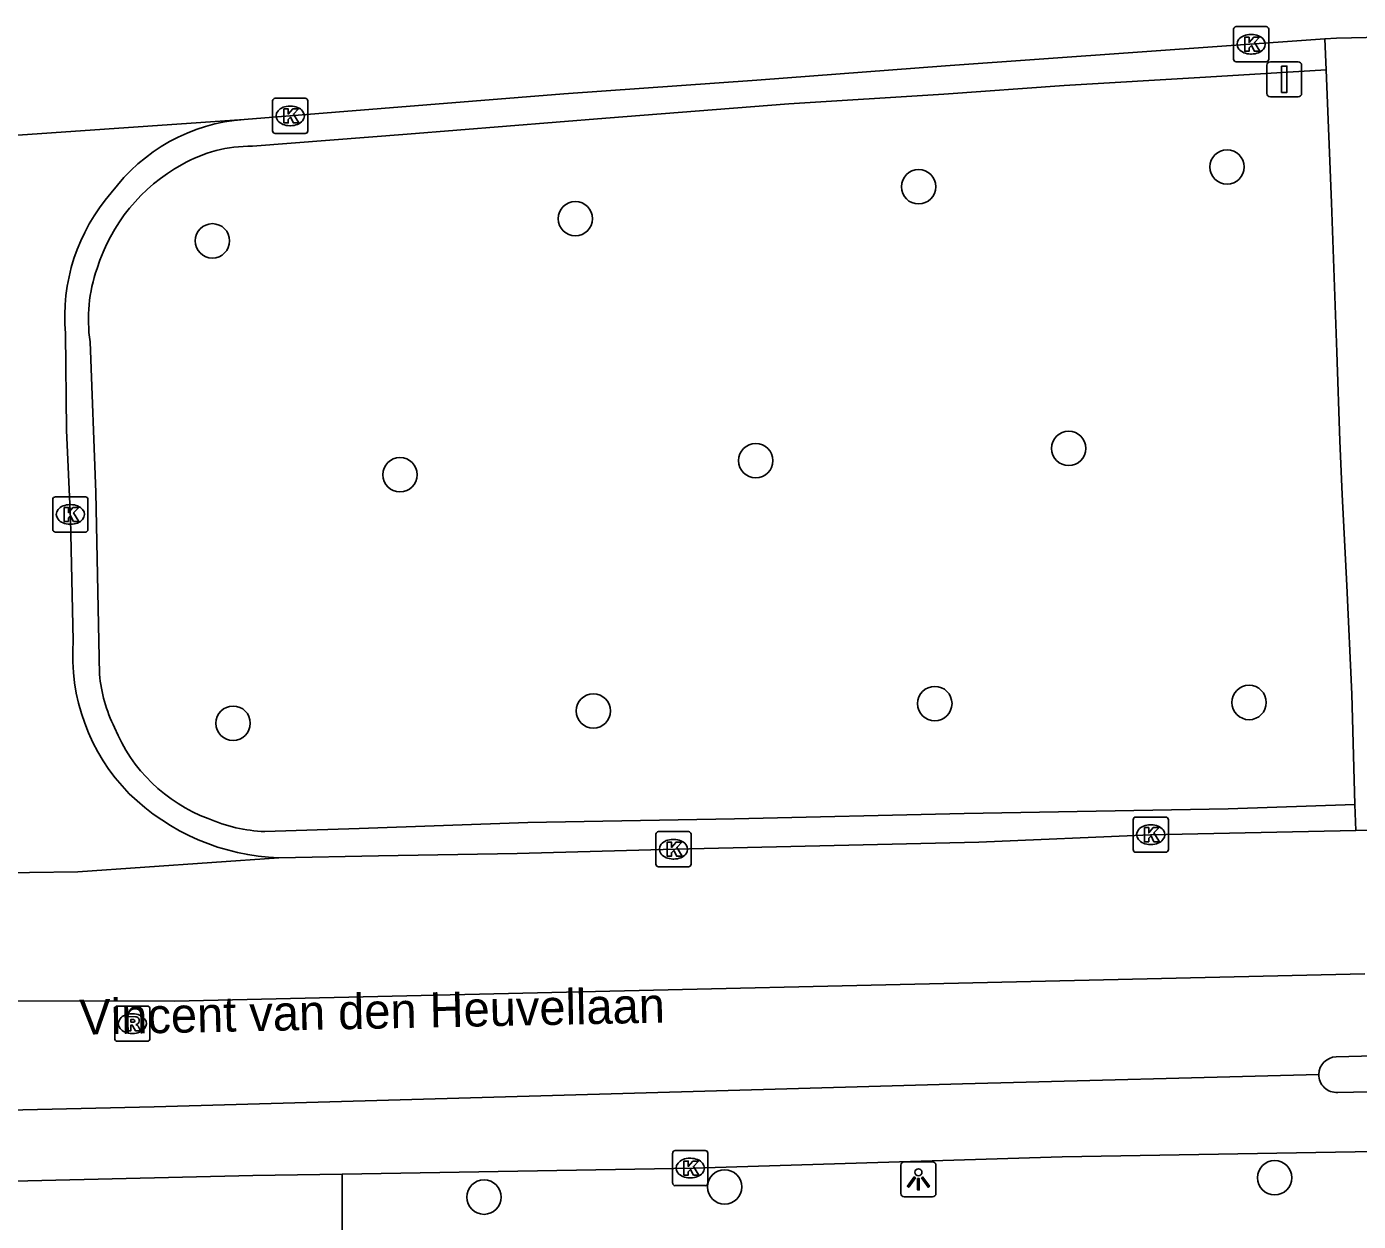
# Model space of a CAD drawing. Extents: x 160806 to 161707, y 383697 to 384148.
# Drawn here: x 161330.97 to 161368.85, y 384111.62 to 384145.6 of the extents above; entities that cross this region are included whole.
import ezdxf

# ---------------------------------------------------------------- set-up
doc = ezdxf.new("R2010")
doc.units = 0
for name, color, linetype in [('IMGEO_Boom', 7, 'Continuous'), ('IMGEO_Kolk', 7, 'Continuous'), ('IMGEO_Lichtpunt', 7, 'Continuous'), ('IMGEO_Openbare_ruimte_label', 7, 'Continuous'), ('IMGEO_Rijbaan_lokaal_gesloten', 7, 'Continuous'), ('IMGEO_Rioolput', 7, 'Continuous'), ('IMGEO_Verkeersbordpaal', 7, 'Continuous'), ('IMGEO_Verkeerseiland_open', 7, 'Continuous'), ('IMGEO_Voetpad_open', 7, 'Continuous')]:
    doc.layers.add(name, color=color, linetype=linetype)

msp = doc.modelspace()

# ---------------------------------------------------------------- linework, layer by layer
at = {"layer": 'IMGEO_Boom'}
for centre in [(161365.116, 384141.61), (161356.343, 384141.046), (161346.581, 384140.138), (161336.259, 384139.508), (161360.612, 384133.603), (161351.712, 384133.255), (161341.593, 384132.854), (161356.804, 384126.346), (161365.743, 384126.376), (161347.092, 384126.136), (161336.846, 384125.786), (161350.826, 384112.597), (161366.469, 384112.857), (161343.983, 384112.305)]:
    msp.add_circle(centre, 0.489, dxfattribs=at)
at = {"layer": 'IMGEO_Kolk'}
for p, q in [((161365.375, 384145.601), (161366.227, 384145.601)), ((161365.3, 384144.675), (161365.3, 384145.527)), ((161365.788, 384145.381), (161365.813, 384145.381)), ((161366.301, 384145.527), (161366.301, 384144.675)), ((161366.227, 384144.601), (161365.375, 384144.601)), ((161365.811, 384144.821), (161365.786, 384144.821)), ((161337.971, 384142.637), (161337.971, 384143.489)), ((161338.046, 384143.563), (161338.898, 384143.563)), ((161338.459, 384143.343), (161338.484, 384143.343)), ((161338.972, 384143.489), (161338.972, 384142.637)), ((161338.482, 384142.783), (161338.457, 384142.783)), ((161338.898, 384142.563), (161338.046, 384142.563)), ((161331.717, 384131.299), (161331.717, 384132.151)), ((161331.792, 384132.225), (161332.644, 384132.225)), ((161332.205, 384132.005), (161332.23, 384132.005)), ((161332.718, 384132.151), (161332.718, 384131.299)), ((161332.644, 384131.225), (161331.792, 384131.225)), ((161332.228, 384131.445), (161332.203, 384131.445)), ((161362.445, 384122.19), (161362.445, 384123.042)), ((161362.52, 384123.116), (161363.372, 384123.116)), ((161362.933, 384122.896), (161362.958, 384122.896)), ((161363.446, 384123.042), (161363.446, 384122.19)), ((161348.871, 384121.777), (161348.871, 384122.629)), ((161348.946, 384122.703), (161349.798, 384122.703)), ((161349.872, 384122.629), (161349.872, 384121.777)), ((161349.359, 384122.483), (161349.384, 384122.483)), ((161363.372, 384122.116), (161362.52, 384122.116)), ((161362.956, 384122.336), (161362.931, 384122.336)), ((161349.382, 384121.923), (161349.357, 384121.923)), ((161349.798, 384121.703), (161348.946, 384121.703)), ((161349.348, 384112.706), (161349.348, 384113.558)), ((161349.423, 384113.632), (161350.275, 384113.632)), ((161349.836, 384113.412), (161349.861, 384113.412)), ((161350.349, 384113.558), (161350.349, 384112.706)), ((161349.859, 384112.852), (161349.834, 384112.852)), ((161350.275, 384112.632), (161349.423, 384112.632))]:
    msp.add_line(p, q, dxfattribs=at)
for points in [[(161365.375, 384145.601), (161366.227, 384145.601)], [(161365.3, 384144.675), (161365.3, 384145.527)], [(161365.621, 384145.301), (161365.744, 384145.301), (161365.744, 384145.15), (161365.874, 384145.301), (161366.038, 384145.301), (161365.892, 384145.15), (161366.045, 384144.901), (161365.893, 384144.901), (161365.808, 384145.065), (161365.744, 384144.998), (161365.744, 384144.901), (161365.621, 384144.901), (161365.621, 384145.301)], [(161366.301, 384145.527), (161366.301, 384144.675)], [(161366.227, 384144.601), (161365.375, 384144.601)], [(161337.971, 384142.637), (161337.971, 384143.489)], [(161338.046, 384143.563), (161338.898, 384143.563)], [(161338.972, 384143.489), (161338.972, 384142.637)], [(161338.292, 384143.263), (161338.415, 384143.263), (161338.415, 384143.112), (161338.545, 384143.263), (161338.709, 384143.263), (161338.563, 384143.112), (161338.716, 384142.863), (161338.564, 384142.863), (161338.479, 384143.027), (161338.415, 384142.96), (161338.415, 384142.863), (161338.292, 384142.863), (161338.292, 384143.263)], [(161338.898, 384142.563), (161338.046, 384142.563)], [(161331.717, 384131.299), (161331.717, 384132.151)], [(161331.792, 384132.225), (161332.644, 384132.225)], [(161332.718, 384132.151), (161332.718, 384131.299)], [(161332.038, 384131.925), (161332.161, 384131.925), (161332.161, 384131.774), (161332.291, 384131.925), (161332.455, 384131.925), (161332.309, 384131.774), (161332.462, 384131.525), (161332.31, 384131.525), (161332.225, 384131.689), (161332.161, 384131.622), (161332.161, 384131.525), (161332.038, 384131.525), (161332.038, 384131.925)], [(161332.644, 384131.225), (161331.792, 384131.225)], [(161362.445, 384122.19), (161362.445, 384123.042)], [(161362.52, 384123.116), (161363.372, 384123.116)], [(161363.446, 384123.042), (161363.446, 384122.19)], [(161348.871, 384121.777), (161348.871, 384122.629)], [(161348.946, 384122.703), (161349.798, 384122.703)], [(161349.872, 384122.629), (161349.872, 384121.777)], [(161362.766, 384122.816), (161362.889, 384122.816), (161362.889, 384122.665), (161363.019, 384122.816), (161363.183, 384122.816), (161363.037, 384122.665), (161363.19, 384122.416), (161363.038, 384122.416), (161362.953, 384122.58), (161362.889, 384122.513), (161362.889, 384122.416), (161362.766, 384122.416), (161362.766, 384122.816)], [(161349.192, 384122.403), (161349.315, 384122.403), (161349.315, 384122.252), (161349.445, 384122.403), (161349.609, 384122.403), (161349.463, 384122.252), (161349.616, 384122.003), (161349.464, 384122.003), (161349.379, 384122.167), (161349.315, 384122.1), (161349.315, 384122.003), (161349.192, 384122.003), (161349.192, 384122.403)], [(161363.372, 384122.116), (161362.52, 384122.116)], [(161349.798, 384121.703), (161348.946, 384121.703)], [(161349.348, 384112.706), (161349.348, 384113.558)], [(161349.423, 384113.632), (161350.275, 384113.632)], [(161350.349, 384113.558), (161350.349, 384112.706)], [(161349.669, 384113.332), (161349.792, 384113.332), (161349.792, 384113.181), (161349.922, 384113.332), (161350.086, 384113.332), (161349.94, 384113.181), (161350.093, 384112.932), (161349.941, 384112.932), (161349.856, 384113.096), (161349.792, 384113.029), (161349.792, 384112.932), (161349.669, 384112.932), (161349.669, 384113.332)], [(161350.275, 384112.632), (161349.423, 384112.632)]]:
    msp.add_lwpolyline(points, dxfattribs=at)
for centre, start, end in [((161365.377, 384145.525), 91.552, 178.448), ((161365.377, 384145.525), 91.552, 178.448), ((161366.225, 384145.525), 1.552, 88.448), ((161366.225, 384145.525), 1.552, 88.448), ((161365.377, 384144.677), 181.552, 268.448), ((161365.377, 384144.677), 181.552, 268.448), ((161366.225, 384144.677), 271.552, 358.448), ((161366.225, 384144.677), 271.552, 358.448), ((161338.048, 384143.487), 91.552, 178.448), ((161338.048, 384143.487), 91.552, 178.448), ((161338.896, 384143.487), 1.552, 88.448), ((161338.896, 384143.487), 1.552, 88.448), ((161338.048, 384142.639), 181.552, 268.448), ((161338.048, 384142.639), 181.552, 268.448), ((161338.896, 384142.639), 271.552, 358.448), ((161338.896, 384142.639), 271.552, 358.448), ((161331.794, 384132.149), 91.552, 178.448), ((161331.794, 384132.149), 91.552, 178.448), ((161332.642, 384132.149), 1.552, 88.448), ((161332.642, 384132.149), 1.552, 88.448), ((161331.794, 384131.301), 181.552, 268.448), ((161331.794, 384131.301), 181.552, 268.448), ((161332.642, 384131.301), 271.552, 358.448), ((161332.642, 384131.301), 271.552, 358.448), ((161362.522, 384123.04), 91.552, 178.448), ((161362.522, 384123.04), 91.552, 178.448), ((161363.37, 384123.04), 1.552, 88.448), ((161363.37, 384123.04), 1.552, 88.448), ((161348.948, 384122.627), 91.552, 178.448), ((161348.948, 384122.627), 91.552, 178.448), ((161349.796, 384122.627), 1.552, 88.448), ((161349.796, 384122.627), 1.552, 88.448), ((161362.522, 384122.192), 181.552, 268.448), ((161362.522, 384122.192), 181.552, 268.448), ((161363.37, 384122.192), 271.552, 358.448), ((161363.37, 384122.192), 271.552, 358.448), ((161348.948, 384121.779), 181.552, 268.448), ((161348.948, 384121.779), 181.552, 268.448), ((161349.796, 384121.779), 271.552, 358.448), ((161349.796, 384121.779), 271.552, 358.448), ((161349.425, 384113.556), 91.552, 178.448), ((161349.425, 384113.556), 91.552, 178.448), ((161350.273, 384113.556), 1.552, 88.448), ((161350.273, 384113.556), 1.552, 88.448), ((161349.425, 384112.708), 181.552, 268.448), ((161349.425, 384112.708), 181.552, 268.448), ((161350.273, 384112.708), 271.552, 358.448), ((161350.273, 384112.708), 271.552, 358.448)]:
    msp.add_arc(centre, 0.0765, start, end, dxfattribs=at)
for centre, major_axis, ratio, start_param, end_param in [((161365.787, 384145.101), (-0.387, 0.002), 0.722429, 4.712389, 7.853982), ((161365.812, 384145.101), (-0.39, 0.002), 0.717154, 1.570796, 4.712389), ((161338.458, 384143.063), (-0.387, 0.002), 0.722429, 4.712389, 7.853982), ((161338.483, 384143.063), (-0.39, 0.002), 0.717154, 1.570796, 4.712389), ((161332.204, 384131.725), (-0.387, 0.002), 0.722429, 4.712389, 7.853982), ((161332.229, 384131.725), (-0.39, 0.002), 0.717154, 1.570796, 4.712389), ((161362.932, 384122.616), (-0.387, 0.002), 0.722429, 4.712389, 7.853982), ((161362.957, 384122.616), (-0.39, 0.002), 0.717154, 1.570796, 4.712389), ((161349.358, 384122.203), (-0.387, 0.002), 0.722429, 4.712389, 7.853982), ((161349.383, 384122.203), (-0.39, 0.002), 0.717154, 1.570796, 4.712389), ((161349.835, 384113.132), (-0.387, 0.002), 0.722429, 4.712389, 7.853982), ((161349.86, 384113.132), (-0.39, 0.002), 0.717154, 1.570796, 4.712389)]:
    msp.add_ellipse(centre, major_axis=major_axis, ratio=ratio, start_param=start_param, end_param=end_param, dxfattribs=at)
at = {"layer": 'IMGEO_Lichtpunt'}
for p, q in [((161355.84, 384113.215), (161355.84, 384112.408)), ((161355.84, 384113.215), (161355.84, 384112.408)), ((161356.742, 384113.31), (161355.934, 384113.31)), ((161356.742, 384113.31), (161355.934, 384113.31)), ((161356.836, 384112.408), (161356.836, 384113.215)), ((161356.836, 384112.408), (161356.836, 384113.215)), ((161355.934, 384112.314), (161356.742, 384112.314)), ((161355.934, 384112.314), (161356.742, 384112.314))]:
    msp.add_line(p, q, dxfattribs=at)
for points in [[(161356.214, 384112.879), (161356.253, 384112.851), (161356.065, 384112.589), (161356.027, 384112.616), (161356.214, 384112.879)], [(161356.316, 384112.831), (161356.363, 384112.831), (161356.363, 384112.509), (161356.316, 384112.509), (161356.316, 384112.831)], [(161356.426, 384112.851), (161356.464, 384112.878), (161356.651, 384112.616), (161356.612, 384112.588), (161356.426, 384112.851)]]:
    msp.add_lwpolyline(points, dxfattribs=at)
msp.add_circle((161356.339, 384113.013), 0.0994, dxfattribs=at)
for centre, start, end in [((161355.934, 384113.215), 90, 180), ((161355.934, 384113.215), 90, 180), ((161356.742, 384113.215), 0, 90), ((161356.742, 384113.215), 0, 90), ((161355.934, 384112.408), 180, 270), ((161355.934, 384112.408), 180, 270), ((161356.742, 384112.408), 270, 0), ((161356.742, 384112.408), 270, 360)]:
    msp.add_arc(centre, 0.0946, start, end, dxfattribs=at)
at = {"layer": 'IMGEO_Rijbaan_lokaal_gesloten'}
for points in [[(161337.16, 384142.963), (161346.257, 384143.694), (161351.743, 384144.08), (161357.112, 384144.482), (161367.896, 384145.252)], [(161367.896, 384145.252), (161368.23, 384145.276), (161372.889, 384145.38)], [(161317.535, 384141.567), (161327.703, 384142.304), (161337.16, 384142.963)], [(161332.082, 384136.87), (161332.111, 384134.119), (161332.223, 384131.597), (161332.301, 384128.136)], [(161338.149, 384121.956), (161340.98, 384122.012), (161344.922, 384122.082), (161349.424, 384122.203), (161358.059, 384122.401), (161362.942, 384122.615), (161368.776, 384122.738)], [(161373.645, 384122.84), (161368.776, 384122.738)], [(161338.149, 384121.956), (161332.428, 384121.56), (161328.301, 384121.504), (161324.44, 384121.451), (161317.569, 384121.54)], [(161260.613, 384121.23), (161278.23, 384120.232), (161293.967, 384119.32), (161308.839, 384118.481), (161316.729, 384118.038), (161322.396, 384117.897), (161335.182, 384117.881), (161369.031, 384118.661)], [(161367.726, 384115.798), (161357.592, 384115.525), (161334.603, 384114.873), (161327.538, 384114.71), (161321.017, 384114.547), (161306.289, 384115.145), (161286.376, 384116.275)], [(161372.197, 384116.403), (161368.215, 384116.296)], [(161368.263, 384115.283), (161372.247, 384115.365)], [(161428.175, 384115.173), (161420.828, 384114.943), (161412.541, 384114.668), (161402.739, 384114.468), (161394.707, 384114.341), (161383.418, 384113.963), (161372.09, 384113.647), (161360.425, 384113.454), (161349.937, 384113.134), (161339.944, 384112.961)], [(161339.944, 384112.961), (161337.406, 384112.917), (161325.397, 384112.64), (161323.478, 384112.593)]]:
    msp.add_lwpolyline(points, dxfattribs=at)
for centre, radius, start, end in [((161337.542, 384137.818), 5.16, 94.2466, 143.7156), ((161337.391, 384137.356), 5.331, 138.745, 185.2292), ((161337.886, 384127.711), 5.601, 175.6469, 224.5599), ((161338.39, 384128.388), 6.437, 225.7072, 267.8533), ((161368.234, 384115.789), 0.508, 92.0985, 178.9464), ((161368.234, 384115.79), 0.508, 179.1481, 273.248)]:
    msp.add_arc(centre, radius, start, end, dxfattribs=at)
at = {"layer": 'IMGEO_Rioolput'}
for p, q in [((161333.48, 384116.814), (161333.48, 384117.666)), ((161333.555, 384117.74), (161334.407, 384117.74)), ((161334.481, 384117.666), (161334.481, 384116.814)), ((161333.968, 384117.52), (161333.993, 384117.52)), ((161333.991, 384116.96), (161333.966, 384116.96)), ((161334.407, 384116.74), (161333.555, 384116.74))]:
    msp.add_line(p, q, dxfattribs=at)
for points in [[(161333.48, 384116.814), (161333.48, 384117.666)], [(161333.555, 384117.74), (161334.407, 384117.74)], [(161334.481, 384117.666), (161334.481, 384116.814)], [(161334.069, 384117.438), (161333.817, 384117.44), (161333.817, 384117.04)], [(161333.817, 384117.04), (161333.941, 384117.04), (161333.941, 384117.202), (161333.952, 384117.202)], [(161333.995, 384117.359), (161333.941, 384117.359), (161333.941, 384117.278)], [(161333.941, 384117.278), (161333.993, 384117.278)], [(161333.999, 384117.173), (161334.07, 384117.04), (161334.21, 384117.04), (161334.145, 384117.166)], [(161334.407, 384116.74), (161333.555, 384116.74)]]:
    msp.add_lwpolyline(points, dxfattribs=at)
for centre, radius, start, end in [((161333.557, 384117.664), 0.0765, 91.552, 178.448), ((161333.557, 384117.664), 0.0765, 91.552, 178.448), ((161334.405, 384117.664), 0.0765, 1.552, 88.448), ((161334.405, 384117.664), 0.0765, 1.552, 88.448), ((161333.951, 384117.149), 0.0533, 26.0293, 88.6989), ((161333.977, 384117.467), 0.19, 274.7715, 282.9687), ((161334.001, 384117.263), 0.0964, 77.0061, 93.1865), ((161334.015, 384117.32), 0.0378, 276.6634, 79.6772), ((161334.068, 384117.328), 0.109, 350.3612, 89.416), ((161334.066, 384117.328), 0.112, 277.5842, 350.9817), ((161334.05, 384117.113), 0.108, 29.5134, 73.7905), ((161333.557, 384116.816), 0.0765, 181.552, 268.448), ((161333.557, 384116.816), 0.0765, 181.552, 268.448), ((161334.405, 384116.816), 0.0765, 271.552, 358.448), ((161334.405, 384116.816), 0.0765, 271.552, 358.448)]:
    msp.add_arc(centre, radius, start, end, dxfattribs=at)
for centre, major_axis, ratio, start_param, end_param in [((161333.967, 384117.24), (-0.387, 0.002), 0.722429, 4.712389, 7.853982), ((161333.992, 384117.24), (-0.39, 0.002), 0.717154, 1.570796, 4.712389)]:
    msp.add_ellipse(centre, major_axis=major_axis, ratio=ratio, start_param=start_param, end_param=end_param, dxfattribs=at)
at = {"layer": 'IMGEO_Verkeersbordpaal'}
for p, q in [((161366.247, 384143.703), (161366.247, 384144.503)), ((161366.247, 384144.503), (161366.247, 384143.703)), ((161366.347, 384144.603), (161367.137, 384144.603)), ((161367.137, 384144.603), (161366.347, 384144.603)), ((161367.237, 384144.503), (161367.237, 384143.703)), ((161367.237, 384143.703), (161367.237, 384144.503)), ((161367.137, 384143.603), (161366.347, 384143.603)), ((161366.347, 384143.603), (161367.137, 384143.603))]:
    msp.add_line(p, q, dxfattribs=at)
msp.add_lwpolyline([(161366.667, 384144.478), (161366.817, 384144.478), (161366.817, 384143.728), (161366.667, 384143.728), (161366.667, 384144.478)], dxfattribs=at)
for centre, start, end in [((161366.347, 384144.503), 90, 180), ((161366.347, 384144.503), 90, 180), ((161367.137, 384144.503), 0, 90), ((161367.137, 384144.503), 360, 90), ((161366.347, 384143.703), 180, 270), ((161366.347, 384143.703), 180, 270), ((161367.137, 384143.703), 270, 0), ((161367.137, 384143.703), 270, 0)]:
    msp.add_arc(centre, 0.1, start, end, dxfattribs=at)
at = {"layer": 'IMGEO_Verkeerseiland_open'}
for points in [[(161337.394, 384142.199), (161341.799, 384142.542), (161347.447, 384142.996), (161352.653, 384143.406), (161357.058, 384143.679), (161360.482, 384143.926), (161364.506, 384144.165), (161367.93, 384144.377)], [(161333.044, 384127.181), (161332.944, 384132.346), (161332.779, 384136.639)], [(161368.747, 384123.478), (161365.144, 384123.353), (161357.641, 384123.218), (161351.108, 384123.068), (161345.225, 384122.958), (161340.431, 384122.791), (161337.75, 384122.702)]]:
    msp.add_lwpolyline(points, dxfattribs=at)
for centre, radius, start, end in [((161337.351, 384138.259), 3.941, 89.3808, 119.716), ((161337.869, 384137.19), 5.126, 118.8204, 162.6198), ((161337.115, 384137.277), 4.383, 160.7646, 188.3704), ((161337.378, 384127.594), 4.354, 185.4426, 206.3586), ((161337.741, 384127.387), 4.6, 202.0341, 249.6037), ((161337.958, 384127.271), 4.574, 246.551, 267.3923)]:
    msp.add_arc(centre, radius, start, end, dxfattribs=at)
at = {"layer": 'IMGEO_Voetpad_open'}
for points in [[(161367.93, 384144.377), (161367.896, 384145.252)], [(161368.747, 384123.478), (161368.664, 384126.609), (161368.52, 384129.702), (161368.389, 384132.294), (161368.322, 384133.815), (161368.24, 384136.337), (161368.083, 384140.59), (161367.93, 384144.377)], [(161368.776, 384122.738), (161368.747, 384123.478)], [(161339.937, 384108.977), (161339.944, 384112.961)]]:
    msp.add_lwpolyline(points, dxfattribs=at)

# ---------------------------------------------------------------- texts
at = {"layer": 'IMGEO_Openbare_ruimte_label'}
msp.add_text('Vincent van den Heuvellaan', height=1, rotation=1.203, dxfattribs=at).set_placement((161332.486, 384116.923))

doc.saveas('drawing.dxf')
